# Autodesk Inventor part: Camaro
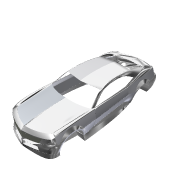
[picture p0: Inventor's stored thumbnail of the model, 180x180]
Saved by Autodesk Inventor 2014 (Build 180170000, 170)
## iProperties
Created: 2015-04
Part Number: Camaro
Material: Steel, Alloy
Document SubType Name: Modeling
Designer: Professor
Density: 7.85 g/cm^3
Appearance: Aluminum - Polished
Sending System: SolidWorks 2010
Last Author: DELL
Author: Professor
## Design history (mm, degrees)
node "Camaro Original 31 Fully completed 31"
thicken "Thicken1" dims "d0" = 1, "d1" = 1
thicken "Thicken2" dims "d2" = 1, "d3" = 1
thicken "Thicken3" dims "d4" = 1, "d5" = 1
thicken "Thicken4" dims "d6" = 1, "d7" = 1
thicken "Thicken5" dims "d8" = 1, "d9" = 1
thicken "Thicken6" dims "d10" = 1, "d11" = 1
thicken "Thicken7" dims "d12" = 1, "d13" = 1
thicken "Thicken8" dims "d14" = 1, "d15" = 1
thicken "Thicken9" dims "d16" = 1, "d17" = 1
thicken "Thicken10" dims "d18" = 1, "d19" = 1
thicken "Thicken11" dims "d20" = 1, "d21" = 1
thicken "Thicken12" dims "d22" = 1, "d23" = 1
thicken "Thicken13" dims "d24" = 1, "d25" = 1
thicken "Thicken14" dims "d26" = 1, "d27" = 1
thicken "Thicken15" dims "d28" = 1, "d29" = 1
thicken "Thicken16" dims "d30" = 1, "d31" = 1
thicken "Thicken17" dims "d32" = 1, "d33" = 1
thicken "Thicken18" dims "d34" = 1, "d35" = 1
thicken "Thicken19" dims "d36" = 1, "d37" = 1
thicken "Thicken20" dims "d38" = 1, "d39" = 1
thicken "Thicken21" dims "d40" = 1, "d41" = 1
thicken "Thicken22" dims "d42" = 1, "d43" = 1
thicken "Thicken23" dims "d44" = 1, "d45" = 1
thicken "Thicken24" dims "d46" = 1, "d47" = 1
thicken "Thicken25" dims "d48" = 1, "d49" = 1
thicken "Thicken26" dims "d50" = 1, "d51" = 1
thicken "Thicken27" dims "d52" = 1, "d53" = 1
thicken "Thicken28" dims "d54" = 1, "d55" = 1
thicken "Thicken29" dims "d56" = 1, "d57" = 1
thicken "Thicken30" dims "d58" = 1, "d59" = 1
thicken "Thicken31" dims "d60" = 1, "d61" = 1
thicken "Thicken32" dims "d62" = 1, "d63" = 1
thicken "Thicken33" dims "d64" = 1, "d65" = 1
thicken "Thicken34" dims "d66" = 1, "d67" = 1
thicken "Thicken35" dims "d68" = 1, "d69" = 1
thicken "Thicken36" dims "d70" = 1, "d71" = 1
thicken "Thicken37" dims "d72" = 1, "d73" = 1
thicken "Thicken38" dims "d74" = 1, "d75" = 1
thicken "Thicken39" dims "d76" = 1, "d77" = 1
thicken "Thicken40" dims "d78" = 1, "d79" = 1
thicken "Thicken41" dims "d80" = 1, "d81" = 1
thicken "Thicken42" dims "d82" = 1, "d83" = 1
thicken "Thicken43" dims "d84" = 1, "d85" = 1
thicken "Thicken44" dims "d86" = 1, "d87" = 1
thicken "Thicken45" dims "d88" = 1, "d89" = 1
thicken "Thicken46" dims "d90" = 1, "d91" = 1
thicken "Thicken47" dims "d92" = 1, "d93" = 1
thicken "Thicken48" dims "d67" = 1, "d94" = 1, "d95" = 1, "d106" = 1, "d108" = 1, "d110" = 1, "d125" = 1, "d133" = 1, "d168" = 1, "d170" = 1, "d172" = 1, "d206" = 1, "d208" = 1, "d210" = 1, "d228" = 1, "d230" = 1, "d232" = 1, "d243" = 5, "d257" = 1, "d279" = 1, "d281" = 1, "d283" = 1, "d290" = 0, "d303" = 1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
thicken "Thicken49" dims "d96" = 1, "d97" = 1
thicken "Thicken50" dims "d98" = 1, "d99" = 1
thicken "Thicken51" dims "d100" = 1, "d101" = 1
thicken "Thicken52" dims "d102" = 1, "d103" = 1
thicken "Thicken53" dims "d104" = 1, "d105" = 1
thicken "Thicken54" dims "d106" = 1, "d107" = 1
thicken "Thicken55" dims "d108" = 1, "d109" = 1
thicken "Thicken56" dims "d110" = 1, "d111" = 1
thicken "Thicken57" dims "d112" = 1, "d113" = 1
thicken "Thicken58" dims "d114" = 1, "d115" = 1
thicken "Thicken59" dims "d116" = 1, "d117" = 1
thicken "Thicken60" dims "d118" = 1, "d119" = 1
thicken "Thicken61" dims "d120" = 1, "d121" = 1
thicken "Thicken62" dims "d122" = 1, "d123" = 1
thicken "Thicken63" dims "d124" = 1, "d125" = 1
thicken "Thicken64" dims "d126" = 1, "d127" = 1
thicken "Thicken65" dims "d128" = 1, "d129" = 1
thicken "Thicken66" dims "d130" = 1, "d131" = 1
thicken "Thicken67" dims "d132" = 1, "d133" = 1
thicken "Thicken68" dims "d134" = 1, "d135" = 1
thicken "Thicken69" dims "d136" = 1, "d137" = 1
thicken "Thicken70" dims "d138" = 1, "d139" = 1
thicken "Thicken71" dims "d140" = 1, "d141" = 1
thicken "Thicken72" dims "d142" = 1, "d143" = 1
thicken "Thicken73" dims "d144" = 1, "d145" = 1
thicken "Thicken74" dims "d146" = 1, "d147" = 1
thicken "Thicken75" dims "d148" = 1, "d149" = 1
thicken "Thicken76" dims "d150" = 1, "d151" = 1
thicken "Thicken77" dims "d152" = 1, "d153" = 1
thicken "Thicken78" dims "d154" = 1, "d155" = 1
thicken "Thicken79" dims "d156" = 1, "d157" = 1
thicken "Thicken80" dims "d158" = 1, "d159" = 1
thicken "Thicken81" dims "d160" = 1, "d161" = 1
thicken "Thicken82" dims "d162" = 1, "d163" = 1
thicken "Thicken83" dims "d164" = 1, "d165" = 1
thicken "Thicken84" dims "d166" = 1, "d167" = 1
thicken "Thicken85" dims "d168" = 1, "d169" = 1
thicken "Thicken86" dims "d170" = 1, "d171" = 1
thicken "Thicken87" dims "d172" = 1, "d173" = 1
thicken "Thicken88" dims "d174" = 1, "d175" = 1
thicken "Thicken89" dims "d176" = 1, "d177" = 1
thicken "Thicken90" dims "d178" = 1, "d179" = 1
thicken "Thicken91" dims "d180" = 1, "d181" = 1
thicken "Thicken92" dims "d182" = 1, "d183" = 1
thicken "Thicken93" dims "d184" = 1, "d185" = 1
thicken "Thicken94" dims "d186" = 1, "d187" = 1
thicken "Thicken95" dims "d188" = 1, "d189" = 1
thicken "Thicken96" dims "d190" = 1, "d191" = 1
thicken "Thicken97" dims "d192" = 1, "d193" = 1
thicken "Thicken98" dims "d194" = 1, "d195" = 1
thicken "Thicken99" dims "d196" = 1, "d197" = 1
thicken "Thicken100" dims "d198" = 1, "d199" = 1
thicken "Thicken101" dims "d200" = 1, "d201" = 1
thicken "Thicken102" dims "d202" = 1, "d203" = 1
thicken "Thicken103" dims "d204" = 1, "d205" = 1
thicken "Thicken104" dims "d206" = 1, "d207" = 1
thicken "Thicken105" dims "d208" = 1, "d209" = 1
thicken "Thicken106" dims "d210" = 1, "d211" = 1
mirror "Mirror1"
thicken "Thicken107" dims "d212" = 1, "d213" = 1
thicken "Thicken108" dims "d214" = 1, "d215" = 1
thicken "Thicken109" dims "d216" = 1, "d217" = 1
thicken "Thicken110" dims "d218" = 1, "d219" = 1
thicken "Thicken111" dims "d220" = 1, "d221" = 1
thicken "Thicken112" dims "d222" = 1, "d223" = 1
thicken "Thicken113" dims "d224" = 1, "d225" = 1
thicken "Thicken114" dims "d226" = 1, "d227" = 1
thicken "Thicken115" dims "d228" = 1, "d229" = 1
thicken "Thicken116" dims "d230" = 1, "d231" = 1
thicken "Thicken117" dims "d232" = 1, "d233" = 1
thicken "Thicken118" dims "d234" = 1, "d235" = 1
thicken "Thicken119" dims "d236" = 1, "d237" = 1
sketch "3D Sketch2"
sketch "3D Sketch3"
patch "Boundary Patch1" sketch "3D Sketch3" dims "d238" = 0
thicken "Thicken120" dims "d239" = 1, "d240" = 1
patch "Boundary Patch2" dims "d241" = 5, "d242" = 5, "d243" = 5, "d244" = 0
thicken "Thicken121" dims "d245" = 1, "d246" = 1
patch "Boundary Patch3" dims "d247" = 5, "d248" = 5, "d249" = 5, "d250" = 0
thicken "Thicken122" dims "d251" = 1, "d252" = 1
thicken "Thicken123" dims "d253" = 1, "d254" = 1
thicken "Thicken124" dims "d255" = 1, "d256" = 1
mirror "Mirror2"
thicken "Thicken125" dims "d257" = 1, "d258" = 1
thicken "Thicken126" dims "d259" = 1, "d260" = 1
feature "OffsetSrf1" dims "d261" = 0, "d262" = 0
feature "OffsetSrf2" dims "d263" = 0, "d264" = 0
feature "OffsetSrf3" dims "d265" = 0, "d266" = 0
feature "OffsetSrf4" dims "d267" = 0, "d268" = 0
thicken "Thicken127" dims "d269" = 0.1, "d270" = 0.1
thicken "Thicken128" dims "d271" = 0.1, "d272" = 0.1
thicken "Thicken129" dims "d273" = 1, "d274" = 1
thicken "Thicken130" dims "d275" = 1, "d276" = 1
thicken "Thicken131" dims "d277" = 1, "d278" = 1
thicken "Thicken132" dims "d279" = 1, "d280" = 1
thicken "Thicken133" dims "d281" = 1, "d282" = 1
thicken "Thicken134" dims "d283" = 1, "d284" = 1
mirror "Mirror3"
patch "Boundary Patch4" dims "d285" = 5, "d286" = 5, "d287" = 5, "d288" = 5, "d289" = 5, "d290" = 0
patch "Boundary Patch5" dims "d291" = 5, "d292" = 5, "d293" = 5, "d294" = 5, "d295" = 5, "d296" = 5, "d297" = 5, "d298" = 0
thicken "Thicken135" dims "d299" = 1, "d300" = 1
thicken "Thicken136" dims "d301" = 1, "d302" = 1
thicken "Thicken137" dims "d303" = 1, "d304" = 1
mirror "Mirror4"
mirror "Mirror5"
sketch "3D Sketch4"
sketch "3D Sketch5"
sketch "3D Sketch6"
patch "Boundary Patch6" sketch "3D Sketch4", "3D Sketch5", "3D Sketch6" dims "d305" = 5, "d306" = 5, "d307" = 5, "d308" = 5, "d309" = 0
thicken "Thicken138" dims "d310" = 0.1, "d311" = 0.1
thicken "Thicken139" dims "d312" = 1, "d313" = 1
thicken "Thicken140" dims "d314" = 1, "d315" = 1
mirror "Mirror6"
mirror "Mirror7"
thicken "Thicken141" dims "d316" = 0.05, "d317" = 0.05
thicken "Thicken142" dims "d318" = 0.05, "d319" = 0.05
mirror "Mirror8"
mirror "Mirror9"
body "Solid1"
body "Solid2"
body "Solid3"
body "Solid4"
body "Solid5"
body "Solid6"
body "Solid7"
body "Solid8"
body "Solid9"
body "Solid10"
body "Solid11"
body "Solid12"
body "Solid13"
body "Solid14"
body "Solid15"
body "Solid16"
body "Solid17"
body "Solid18"
body "Solid19"
body "Solid20"
body "Solid21"
body "Solid22"
body "Solid23"
body "Solid24"
body "Solid25"
body "Solid26"
body "Solid27"
body "Solid28"
body "Solid29"
body "Solid30"
body "Solid31"
body "Solid32"
body "Solid33"
body "Solid34"
body "Solid35"
body "Solid36"
body "Solid37"
body "Solid38"
body "Solid39"
body "Solid40"
body "Solid41"
body "Solid42"
body "Solid43"
body "Solid44"
body "Solid45"
body "Solid46"
body "Solid47"
body "Solid48"
body "Solid49"
body "Solid50"
body "Solid51"
body "Solid52"
body "Solid53"
body "Solid54"
body "Solid55"
body "Solid56"
body "Solid57"
body "Solid58"
body "Solid59"
body "Solid60"
body "Solid61"
body "Solid62"
body "Solid63"
body "Solid64"
body "Solid65"
body "Solid66"
body "Solid67"
body "Solid68"
body "Solid69"
body "Solid70"
body "Solid71"
body "Solid72"
body "Solid73"
body "Solid74"
body "Solid75"
body "Solid76"
body "Solid77"
body "Solid78"
body "Solid79"
body "Solid80"
body "Solid81"
body "Solid82"
body "Solid83"
body "Solid84"
body "Solid85"
body "Solid86"
body "Solid87"
body "Solid88"
body "Solid89"
body "Solid90"
body "Solid91"
body "Solid92"
body "Solid93"
body "Solid94"
body "Solid95"
body "Solid96"
body "Solid97"
body "Solid98"
body "Solid99"
body "Solid100"
body "Solid101"
body "Solid102"
body "Solid103"
body "Solid104"
body "Solid105"
body "Solid106"
body "Solid107"
body "Solid108"
body "Solid109"
body "Solid110"
body "Srf2"
body "Solid111"
body "Srf3"
body "Solid112"
body "Srf4"
body "Solid113"
body "Solid114"
body "Solid115"
body "Solid116"
body "Solid117"
body "Srf5"
body "Srf6"
body "Srf7"
body "Srf8"
body "Solid118"
body "Solid119"
body "Solid120"
body "Solid121"
body "Solid122"
body "Solid123"
body "Solid124"
body "Solid125"
body "Srf9"
body "Srf10"
body "Solid126"
body "Solid127"
body "Solid128"
body "Srf11"
body "Solid129"
body "Solid130"
body "Solid131"
body "Solid132"
body "Solid133"
feature "Composite1"
body "Srf1"
